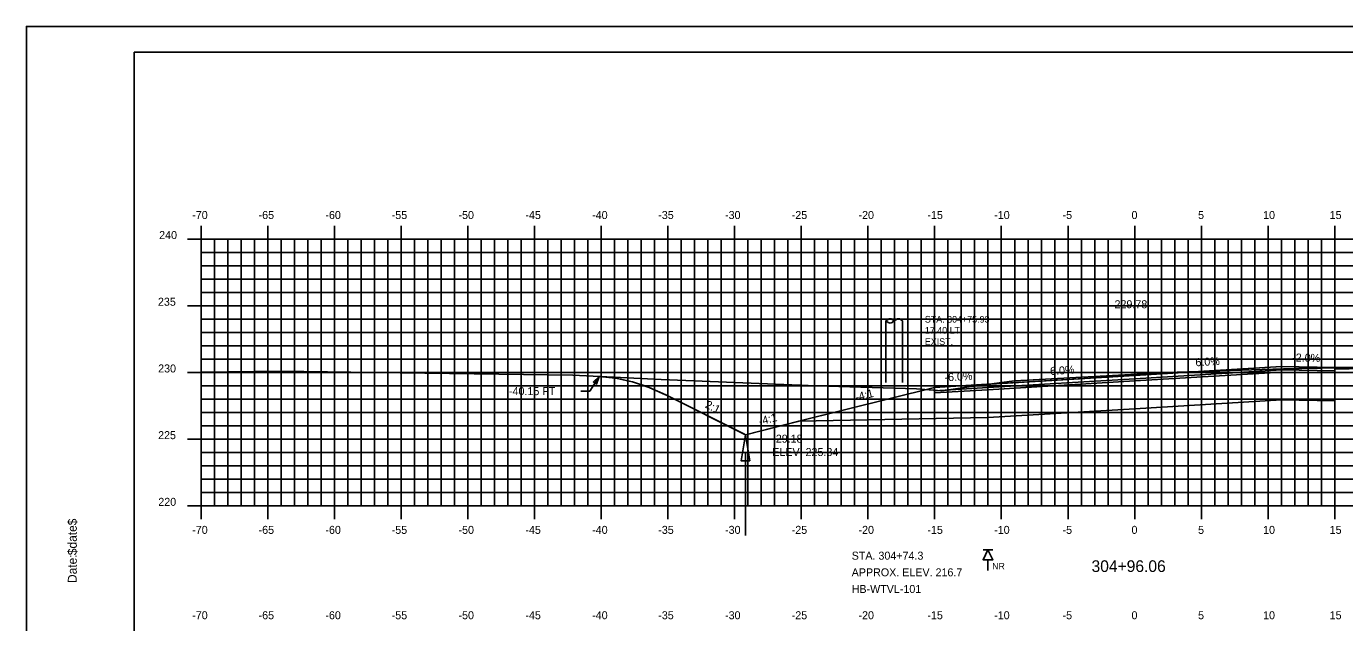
# Model space of a CAD drawing. Extents: x 1136989 to 1137159, y 608981 to 609091.
# Drawn here: x 1136989 to 1137087.9, y 609046.6 to 609091.3 of the extents above; entities that cross this region are included whole.
import ezdxf

# ---------------------------------------------------------------- set-up
doc = ezdxf.new("R2010")
doc.units = 0
for name, color, linetype in [('ANNOTATION', 7, 'Continuous'), ('BORDER', 7, 'Continuous'), ('D_Drainage_Ditch_Line', 7, 'Continuous'), ('D_Roadway_Centerline', 7, 'Continuous'), ('D_Roadway_Centerline_Text', 7, 'Continuous'), ('D_Roadway_Edge_Shoulder', 7, 'Continuous'), ('D_Roadway_Edge_TW', 7, 'Continuous'), ('D_Roadway_Pavement', 7, 'Continuous'), ('D_Roadway_SlopeLines', 7, 'Continuous'), ('D_Roadway_SubGrade', 7, 'Continuous'), ('D_Text_Monospaced', 7, 'Continuous'), ('D_Text_Standard', 7, 'Continuous'), ('H_V ANNOTATION', 7, 'Continuous'), ('MAJOR', 7, 'Continuous'), ('MINOR', 7, 'Continuous'), ('PLOT BOUNDARY', 7, 'Continuous'), ('ROCKS', 7, 'Continuous'), ('S_Roadway_Centerline', 7, 'Continuous'), ('S_Utilities_Pole_StreetLight', 7, 'Continuous')]:
    doc.layers.add(name, color=color, linetype=linetype)

msp = doc.modelspace()

# ---------------------------------------------------------------- linework, layer by layer
msp.add_lwpolyline([(1137031.994, 609065.033), (1137033.218, 609064.903), (1137033.244, 609064.9), (1137034.468, 609064.631), (1137034.494, 609064.626), (1137035.718, 609064.22), (1137035.744, 609064.211), (1137036.968, 609063.668), (1137036.994, 609063.656), (1137042.843, 609060.732), (1137042.965, 609060.671), (1137046.883, 609061.651), (1137046.965, 609061.671), (1137047.168, 609061.722), (1137057.139, 609064.215), (1137057.14, 609064.215), (1137057.14, 609064.215), (1137061.058, 609064.45), (1137061.14, 609064.455), (1137061.359, 609064.468), (1137072.14, 609065.115), (1137072.359, 609065.128), (1137083.14, 609065.775), (1137087.058, 609065.696), (1137087.14, 609065.695)])
at = {"layer": 'BORDER'}
msp.add_lwpolyline([(1136997.14, 608984.335), (1137157.14, 608984.335), (1137157.14, 609089.335), (1136997.14, 609089.335)], close=True, dxfattribs=at)
at = {"layer": 'D_Drainage_Ditch_Line'}
msp.add_line((1137042.965, 609059.359), (1137042.964, 609053.115), dxfattribs=at)
msp.add_lwpolyline([(1137043.293, 609058.702), (1137042.637, 609058.702), (1137042.965, 609060.671)], close=True, dxfattribs=at)
at = {"layer": 'D_Roadway_Edge_Shoulder'}
msp.add_line((1137087.14, 609065.695), (1137126.61, 609066.625), dxfattribs=at)
msp.add_lwpolyline([(1137133.61, 609066.625), (1137133.61, 609066.5), (1137126.61, 609066.5), (1137087.14, 609065.57)], dxfattribs=at)
for points in [[(1137083.14, 609065.775), (1137087.14, 609065.695), (1137087.14, 609065.445), (1137083.14, 609065.525)], [(1137061.14, 609064.455), (1137057.14, 609064.215), (1137057.14, 609063.965), (1137061.14, 609064.205)]]:
    msp.add_lwpolyline(points, close=True, dxfattribs=at)
at = {"layer": 'D_Roadway_Edge_TW'}
for points in [[(1137061.14, 609064.205), (1137061.14, 609064.455), (1137072.14, 609065.115), (1137083.14, 609065.775), (1137083.14, 609065.525), (1137072.14, 609064.865)], [(1137061.14, 609064.038), (1137057.14, 609063.798), (1137057.14, 609063.965), (1137061.14, 609064.205)]]:
    msp.add_lwpolyline(points, close=True, dxfattribs=at)
at = {"layer": 'D_Roadway_Pavement'}
msp.add_lwpolyline([(1137061.14, 609064.038), (1137061.14, 609064.205), (1137072.14, 609064.865), (1137083.14, 609065.525), (1137083.14, 609065.358), (1137072.14, 609064.698)], close=True, dxfattribs=at)
at = {"layer": 'D_Roadway_SlopeLines'}
for points in [[(1137042.965, 609060.671), (1137036.994, 609063.656), (1137035.744, 609064.211), (1137034.494, 609064.626), (1137033.244, 609064.9), (1137031.994, 609065.033)], [(1137046.965, 609061.671), (1137042.965, 609060.671)]]:
    msp.add_lwpolyline(points, dxfattribs=at)
at = {"layer": 'D_Roadway_SubGrade'}
for points in [[(1137061.14, 609061.954), (1137061.14, 609064.038), (1137072.14, 609064.698), (1137083.14, 609065.358), (1137083.14, 609063.275), (1137072.14, 609062.615)], [(1137087.14, 609064.695), (1137087.14, 609065.695), (1137087.14, 609065.695), (1137087.14, 609065.445), (1137083.14, 609065.525), (1137083.14, 609065.358), (1137083.14, 609063.275), (1137087.14, 609063.195)], [(1137061.14, 609064.038), (1137061.14, 609064.205), (1137057.14, 609063.965), (1137057.14, 609064.215), (1137057.139, 609064.215), (1137046.965, 609061.671), (1137061.14, 609061.954)]]:
    msp.add_lwpolyline(points, close=True, dxfattribs=at)
at = {"layer": 'D_Text_Standard'}
msp.add_lwpolyline([(1137031.994, 609065.033), (1137031.289, 609063.935), (1137030.609, 609063.935)], dxfattribs=at)
msp.add_lwpolyline([(1137031.994, 609065.033), (1137031.802, 609064.465), (1137031.557, 609064.622)], close=True, dxfattribs=at)
at = {"layer": 'MAJOR'}
for p, q in [((1137002.14, 609076.337), (1137002.14, 609075.335)), ((1137007.14, 609076.337), (1137007.14, 609075.335)), ((1137012.14, 609076.337), (1137012.14, 609075.335)), ((1137017.14, 609076.337), (1137017.14, 609075.335)), ((1137022.14, 609076.337), (1137022.14, 609075.335)), ((1137027.14, 609076.337), (1137027.14, 609075.335)), ((1137032.14, 609076.337), (1137032.14, 609075.335)), ((1137037.14, 609076.337), (1137037.14, 609075.335)), ((1137042.14, 609076.337), (1137042.14, 609075.335)), ((1137047.14, 609076.337), (1137047.14, 609075.335)), ((1137052.14, 609076.337), (1137052.14, 609075.335)), ((1137057.14, 609076.337), (1137057.14, 609075.335)), ((1137062.14, 609076.337), (1137062.14, 609075.335)), ((1137067.14, 609076.337), (1137067.14, 609075.335)), ((1137072.14, 609076.337), (1137072.14, 609075.335)), ((1137077.14, 609076.337), (1137077.14, 609075.335)), ((1137082.14, 609076.337), (1137082.14, 609075.335)), ((1137087.14, 609076.337), (1137087.14, 609075.335)), ((1137001.138, 609075.335), (1137002.14, 609075.335)), ((1137002.14, 609075.335), (1137142.14, 609075.335)), ((1137002.14, 609055.335), (1137002.14, 609075.335)), ((1137002.14, 609055.335), (1137002.14, 609075.335)), ((1137002.14, 609075.335), (1137142.14, 609075.335)), ((1137007.14, 609055.335), (1137007.14, 609075.335)), ((1137012.14, 609055.335), (1137012.14, 609075.335)), ((1137017.14, 609055.335), (1137017.14, 609075.335)), ((1137022.14, 609055.335), (1137022.14, 609075.335)), ((1137027.14, 609055.335), (1137027.14, 609075.335)), ((1137032.14, 609055.335), (1137032.14, 609075.335)), ((1137037.14, 609055.335), (1137037.14, 609075.335)), ((1137042.14, 609055.335), (1137042.14, 609075.335)), ((1137047.14, 609055.335), (1137047.14, 609075.335)), ((1137052.14, 609055.335), (1137052.14, 609075.335)), ((1137057.14, 609055.335), (1137057.14, 609075.335)), ((1137062.14, 609055.335), (1137062.14, 609075.335)), ((1137067.14, 609055.335), (1137067.14, 609075.335)), ((1137072.14, 609055.335), (1137072.14, 609075.335)), ((1137077.14, 609055.335), (1137077.14, 609075.335)), ((1137082.14, 609055.335), (1137082.14, 609075.335)), ((1137087.14, 609055.335), (1137087.14, 609075.335)), ((1137001.138, 609070.335), (1137002.14, 609070.335)), ((1137002.14, 609070.335), (1137142.14, 609070.335)), ((1137001.138, 609065.335), (1137002.14, 609065.335)), ((1137002.14, 609065.335), (1137142.14, 609065.335)), ((1137001.138, 609060.335), (1137002.14, 609060.335)), ((1137002.14, 609060.335), (1137142.14, 609060.335)), ((1137001.138, 609055.335), (1137002.14, 609055.335)), ((1137002.14, 609055.335), (1137142.14, 609055.335)), ((1137002.14, 609055.335), (1137142.14, 609055.335)), ((1137002.14, 609054.333), (1137002.14, 609055.335)), ((1137007.14, 609054.333), (1137007.14, 609055.335)), ((1137012.14, 609054.333), (1137012.14, 609055.335)), ((1137017.14, 609054.333), (1137017.14, 609055.335)), ((1137022.14, 609054.333), (1137022.14, 609055.335)), ((1137027.14, 609054.333), (1137027.14, 609055.335)), ((1137032.14, 609054.333), (1137032.14, 609055.335)), ((1137037.14, 609054.333), (1137037.14, 609055.335)), ((1137042.14, 609054.333), (1137042.14, 609055.335)), ((1137047.14, 609054.333), (1137047.14, 609055.335)), ((1137052.14, 609054.333), (1137052.14, 609055.335)), ((1137057.14, 609054.333), (1137057.14, 609055.335)), ((1137062.14, 609054.333), (1137062.14, 609055.335)), ((1137067.14, 609054.333), (1137067.14, 609055.335)), ((1137072.14, 609054.333), (1137072.14, 609055.335)), ((1137077.14, 609054.333), (1137077.14, 609055.335)), ((1137082.14, 609054.333), (1137082.14, 609055.335)), ((1137087.14, 609054.333), (1137087.14, 609055.335))]:
    msp.add_line(p, q, dxfattribs=at)
at = {"layer": 'MINOR'}
for p, q in [((1137002.14, 609055.335), (1137002.14, 609075.335)), ((1137003.14, 609055.335), (1137003.14, 609075.335)), ((1137004.14, 609055.335), (1137004.14, 609075.335)), ((1137005.14, 609055.335), (1137005.14, 609075.335)), ((1137006.14, 609055.335), (1137006.14, 609075.335)), ((1137008.14, 609055.335), (1137008.14, 609075.335)), ((1137009.14, 609055.335), (1137009.14, 609075.335)), ((1137010.14, 609055.335), (1137010.14, 609075.335)), ((1137011.14, 609055.335), (1137011.14, 609075.335)), ((1137013.14, 609055.335), (1137013.14, 609075.335)), ((1137014.14, 609055.335), (1137014.14, 609075.335)), ((1137015.14, 609055.335), (1137015.14, 609075.335)), ((1137016.14, 609055.335), (1137016.14, 609075.335)), ((1137018.14, 609055.335), (1137018.14, 609075.335)), ((1137019.14, 609055.335), (1137019.14, 609075.335)), ((1137020.14, 609055.335), (1137020.14, 609075.335)), ((1137021.14, 609055.335), (1137021.14, 609075.335)), ((1137023.14, 609055.335), (1137023.14, 609075.335)), ((1137024.14, 609055.335), (1137024.14, 609075.335)), ((1137025.14, 609055.335), (1137025.14, 609075.335)), ((1137026.14, 609055.335), (1137026.14, 609075.335)), ((1137028.14, 609055.335), (1137028.14, 609075.335)), ((1137029.14, 609055.335), (1137029.14, 609075.335)), ((1137030.14, 609055.335), (1137030.14, 609075.335)), ((1137031.14, 609055.335), (1137031.14, 609075.335)), ((1137033.14, 609055.335), (1137033.14, 609075.335)), ((1137034.14, 609055.335), (1137034.14, 609075.335)), ((1137035.14, 609055.335), (1137035.14, 609075.335)), ((1137036.14, 609055.335), (1137036.14, 609075.335)), ((1137038.14, 609055.335), (1137038.14, 609075.335)), ((1137039.14, 609055.335), (1137039.14, 609075.335)), ((1137040.14, 609055.335), (1137040.14, 609075.335)), ((1137041.14, 609055.335), (1137041.14, 609075.335)), ((1137043.14, 609055.335), (1137043.14, 609075.335)), ((1137044.14, 609055.335), (1137044.14, 609075.335)), ((1137045.14, 609055.335), (1137045.14, 609075.335)), ((1137046.14, 609055.335), (1137046.14, 609075.335)), ((1137048.14, 609055.335), (1137048.14, 609075.335)), ((1137049.14, 609055.335), (1137049.14, 609075.335)), ((1137050.14, 609055.335), (1137050.14, 609075.335)), ((1137051.14, 609055.335), (1137051.14, 609075.335)), ((1137053.14, 609055.335), (1137053.14, 609075.335)), ((1137054.14, 609055.335), (1137054.14, 609075.335)), ((1137055.14, 609055.335), (1137055.14, 609075.335)), ((1137056.14, 609055.335), (1137056.14, 609075.335)), ((1137058.14, 609055.335), (1137058.14, 609075.335)), ((1137059.14, 609055.335), (1137059.14, 609075.335)), ((1137060.14, 609055.335), (1137060.14, 609075.335)), ((1137061.14, 609055.335), (1137061.14, 609075.335)), ((1137063.14, 609055.335), (1137063.14, 609075.335)), ((1137064.14, 609055.335), (1137064.14, 609075.335)), ((1137065.14, 609055.335), (1137065.14, 609075.335)), ((1137066.14, 609055.335), (1137066.14, 609075.335)), ((1137068.14, 609055.335), (1137068.14, 609075.335)), ((1137069.14, 609055.335), (1137069.14, 609075.335)), ((1137070.14, 609055.335), (1137070.14, 609075.335)), ((1137071.14, 609055.335), (1137071.14, 609075.335)), ((1137073.14, 609055.335), (1137073.14, 609075.335)), ((1137074.14, 609055.335), (1137074.14, 609075.335)), ((1137075.14, 609055.335), (1137075.14, 609075.335)), ((1137076.14, 609055.335), (1137076.14, 609075.335)), ((1137078.14, 609055.335), (1137078.14, 609075.335)), ((1137079.14, 609055.335), (1137079.14, 609075.335)), ((1137080.14, 609055.335), (1137080.14, 609075.335)), ((1137081.14, 609055.335), (1137081.14, 609075.335)), ((1137083.14, 609055.335), (1137083.14, 609075.335)), ((1137084.14, 609055.335), (1137084.14, 609075.335)), ((1137085.14, 609055.335), (1137085.14, 609075.335)), ((1137086.14, 609055.335), (1137086.14, 609075.335)), ((1137002.14, 609074.335), (1137142.14, 609074.335)), ((1137002.14, 609074.335), (1137003.142, 609074.335)), ((1137002.14, 609073.335), (1137142.14, 609073.335)), ((1137002.14, 609073.335), (1137003.142, 609073.335)), ((1137002.14, 609072.335), (1137142.14, 609072.335)), ((1137002.14, 609072.335), (1137003.142, 609072.335)), ((1137002.14, 609071.335), (1137142.14, 609071.335)), ((1137002.14, 609071.335), (1137003.142, 609071.335)), ((1137002.14, 609069.335), (1137142.14, 609069.335)), ((1137002.14, 609069.335), (1137003.142, 609069.335)), ((1137002.14, 609068.335), (1137142.14, 609068.335)), ((1137002.14, 609068.335), (1137003.142, 609068.335)), ((1137002.14, 609067.335), (1137142.14, 609067.335)), ((1137002.14, 609067.335), (1137003.142, 609067.335)), ((1137002.14, 609066.335), (1137142.14, 609066.335)), ((1137002.14, 609066.335), (1137003.142, 609066.335)), ((1137002.14, 609064.335), (1137142.14, 609064.335)), ((1137002.14, 609064.335), (1137003.142, 609064.335)), ((1137002.14, 609063.335), (1137142.14, 609063.335)), ((1137002.14, 609063.335), (1137003.142, 609063.335)), ((1137002.14, 609062.335), (1137142.14, 609062.335)), ((1137002.14, 609062.335), (1137003.142, 609062.335)), ((1137002.14, 609061.335), (1137142.14, 609061.335)), ((1137002.14, 609061.335), (1137003.142, 609061.335)), ((1137002.14, 609059.335), (1137142.14, 609059.335)), ((1137002.14, 609059.335), (1137003.142, 609059.335)), ((1137002.14, 609058.335), (1137142.14, 609058.335)), ((1137002.14, 609058.335), (1137003.142, 609058.335)), ((1137002.14, 609057.335), (1137142.14, 609057.335)), ((1137002.14, 609057.335), (1137003.142, 609057.335)), ((1137002.14, 609056.335), (1137142.14, 609056.335)), ((1137002.14, 609056.335), (1137003.142, 609056.335))]:
    msp.add_line(p, q, dxfattribs=at)
at = {"layer": 'PLOT BOUNDARY'}
msp.add_lwpolyline([(1136989.047, 608981.276), (1137159.047, 608981.276), (1137159.047, 609091.276), (1136989.047, 609091.276)], close=True, dxfattribs=at)
at = {"layer": 'ROCKS'}
for p, q in [((1137061.509, 609052.035), (1137060.771, 609052.035)), ((1137061.14, 609051.297), (1137061.14, 609050.482))]:
    msp.add_line(p, q, dxfattribs=at)
msp.add_lwpolyline([(1137061.14, 609052.035), (1137061.509, 609051.297), (1137060.771, 609051.297)], close=True, dxfattribs=at)
at = {"layer": 'S_Roadway_Centerline'}
msp.add_lwpolyline([(1137002.14, 609065.362), (1137008.088, 609065.421), (1137013.376, 609065.363), (1137030.013, 609065.134), (1137036.636, 609064.798), (1137048.284, 609064.337), (1137055.773, 609064.114), (1137057.687, 609063.955), (1137059.915, 609064.293), (1137062.94, 609064.669), (1137063.163, 609064.709), (1137071.848, 609065.191), (1137074.524, 609065.325), (1137084.091, 609065.627), (1137084.658, 609065.643), (1137088.834, 609065.696), (1137094.726, 609065.766), (1137095.971, 609065.787), (1137113.166, 609066.129), (1137113.321, 609066.132), (1137113.518, 609066.138), (1137113.761, 609066.144), (1137114.049, 609066.152), (1137142.14, 609066.832)], dxfattribs=at)
at = {"layer": 'S_Utilities_Pole_StreetLight'}
for p, q in [((1137053.489, 609069.193), (1137053.645, 609069.304)), ((1137053.489, 609064.574), (1137053.492, 609069.193)), ((1137053.645, 609069.082), (1137053.489, 609069.193)), ((1137053.957, 609069.304), (1137054.114, 609069.193)), ((1137054.114, 609069.193), (1137053.957, 609069.082)), ((1137054.27, 609069.304), (1137054.114, 609069.193)), ((1137054.739, 609069.193), (1137054.582, 609069.304)), ((1137054.739, 609064.574), (1137054.742, 609069.193))]:
    msp.add_line(p, q, dxfattribs=at)
for centre, start, end in [((1137053.801, 609069.083), 90, 125.26439), ((1137053.801, 609069.304), 234.73561, 270), ((1137053.801, 609069.083), 54.73561, 90), ((1137053.801, 609069.304), 270, 305.26439), ((1137054.426, 609069.083), 90, 125.26439), ((1137054.426, 609069.083), 54.73561, 90)]:
    msp.add_arc(centre, 0.271, start, end, dxfattribs=at)

# ---------------------------------------------------------------- texts
at = {"layer": 'ANNOTATION'}
for s, rotation, p in [('6.0%', 3.43362, (1137076.707, 609065.79)), ('-2.0%', 358.85423, (1137083.942, 609066.159)), ('-6.0%', 3.43362, (1137057.896, 609064.662)), ('-6.0%', 3.43362, (1137065.547, 609065.121)), ('-4:1', 14.03623, (1137051.265, 609063.177)), ('2:1', 333.43494, (1137039.885, 609062.729)), ('-4:1', 14.03623, (1137044.036, 609061.37))]:
    msp.add_text(s, height=0.6, rotation=rotation, dxfattribs=at).set_placement(p)
at = {"layer": 'BORDER'}
for s, p in [('$date$', (1136992.825, 609051.64)), ('Date:', (1136992.825, 609049.552))]:
    msp.add_text(s, height=0.6696, rotation=90, dxfattribs=at).set_placement(p)
at = {"layer": 'D_Roadway_Centerline'}
for s, p in [('C', (1137072.135, 609065.115)), ('L', (1137072.14, 609065.107))]:
    msp.add_text(s, height=0.0146, dxfattribs=at).set_placement(p)
at = {"layer": 'D_Roadway_Centerline_Text'}
msp.add_text('229.78', height=0.6, dxfattribs=at).set_placement((1137070.628, 609070.147))
at = {"layer": 'D_Text_Monospaced'}
for s, height, p in [('STA. 304+75.93', 0.49998, (1137056.405, 609069.072)), ('17.40 LT.', 0.5, (1137056.405, 609068.238)), ('EXIST. ', 0.5, (1137056.405, 609067.398))]:
    msp.add_text(s, height=height, dxfattribs=at).set_placement(p)
at = {"layer": 'D_Text_Standard'}
for s, p in [('-40.15 FT', (1137025.229, 609063.635)), ('-29.18', (1137044.965, 609060.071)), ('ELEV. 225.34', (1137044.965, 609059.069))]:
    msp.add_text(s, height=0.6, dxfattribs=at).set_placement(p)
at = {"layer": 'H_V ANNOTATION'}
for s, height, p in [('-70', 0.6, (1137001.481, 609076.835)), ('-65', 0.6, (1137006.457, 609076.835)), ('-60', 0.6, (1137011.465, 609076.835)), ('-55', 0.6, (1137016.436, 609076.835)), ('-50', 0.6, (1137021.444, 609076.835)), ('-45', 0.6, (1137026.457, 609076.835)), ('-40', 0.6, (1137031.465, 609076.835)), ('-35', 0.6, (1137036.42, 609076.835)), ('-30', 0.6, (1137041.428, 609076.835)), ('-25', 0.6, (1137046.425, 609076.835)), ('-20', 0.6, (1137051.433, 609076.835)), ('-15', 0.6, (1137056.597, 609076.835)), ('-10', 0.6, (1137061.605, 609076.835)), ('-5', 0.6, (1137066.73, 609076.835)), ('0', 0.6, (1137071.899, 609076.835)), ('5', 0.6, (1137076.891, 609076.835)), ('10', 0.6, (1137081.765, 609076.835)), ('15', 0.6, (1137086.757, 609076.835)), ('240', 0.6, (1136999.002, 609075.335)), ('235', 0.6, (1136998.911, 609070.335)), ('230', 0.6, (1136998.927, 609065.335)), ('225', 0.6, (1136998.922, 609060.335)), ('220', 0.6, (1136998.938, 609055.335)), ('-70', 0.6, (1137001.481, 609053.235)), ('-65', 0.6, (1137006.457, 609053.235)), ('-60', 0.6, (1137011.465, 609053.235)), ('-55', 0.6, (1137016.436, 609053.235)), ('-50', 0.6, (1137021.444, 609053.235)), ('-45', 0.6, (1137026.457, 609053.235)), ('-40', 0.6, (1137031.465, 609053.235)), ('-35', 0.6, (1137036.42, 609053.235)), ('-30', 0.6, (1137041.428, 609053.235)), ('-25', 0.6, (1137046.425, 609053.235)), ('-20', 0.6, (1137051.433, 609053.235)), ('-15', 0.6, (1137056.597, 609053.235)), ('-10', 0.6, (1137061.605, 609053.235)), ('-5', 0.6, (1137066.73, 609053.235)), ('0', 0.6, (1137071.899, 609053.235)), ('5', 0.6, (1137076.891, 609053.235)), ('10', 0.6, (1137081.765, 609053.235)), ('15', 0.6, (1137086.757, 609053.235)), ('304+96.06', 0.875, (1137068.902, 609050.378)), ('-70', 0.6, (1137001.481, 609046.835)), ('-65', 0.6, (1137006.457, 609046.835)), ('-60', 0.6, (1137011.465, 609046.835)), ('-55', 0.6, (1137016.436, 609046.835)), ('-50', 0.6, (1137021.444, 609046.835)), ('-45', 0.6, (1137026.457, 609046.835)), ('-40', 0.6, (1137031.465, 609046.835)), ('-35', 0.6, (1137036.42, 609046.835)), ('-30', 0.6, (1137041.428, 609046.835)), ('-25', 0.6, (1137046.425, 609046.835)), ('-20', 0.6, (1137051.433, 609046.835)), ('-15', 0.6, (1137056.597, 609046.835)), ('-10', 0.6, (1137061.605, 609046.835)), ('-5', 0.6, (1137066.73, 609046.835)), ('0', 0.6, (1137071.899, 609046.835)), ('5', 0.6, (1137076.891, 609046.835)), ('10', 0.6, (1137081.765, 609046.835)), ('15', 0.6, (1137086.757, 609046.835))]:
    msp.add_text(s, height=height, dxfattribs=at).set_placement(p)
at = {"layer": 'MAJOR'}
msp.add_text('-', height=0.006, dxfattribs=at).set_placement((1137002.135, 609055.335))
at = {"layer": 'ROCKS'}
for s, p in [('STA. 304+74.3', (1137050.921, 609051.302)), ('APPROX. ELEV. 216.7', (1137050.921, 609050.052)), ('HB-WTVL-101', (1137050.921, 609048.802))]:
    msp.add_text(s, height=0.6, rotation=360, dxfattribs=at).set_placement(p)
msp.add_text('NR', height=0.4921, dxfattribs=at).set_placement((1137061.455, 609050.57))
at = {"layer": 'S_Roadway_Centerline'}
for s, p in [('C', (1137074.519, 609065.325)), ('L', (1137074.524, 609065.317))]:
    msp.add_text(s, height=0.0146, dxfattribs=at).set_placement(p)

doc.saveas('drawing.dxf')
